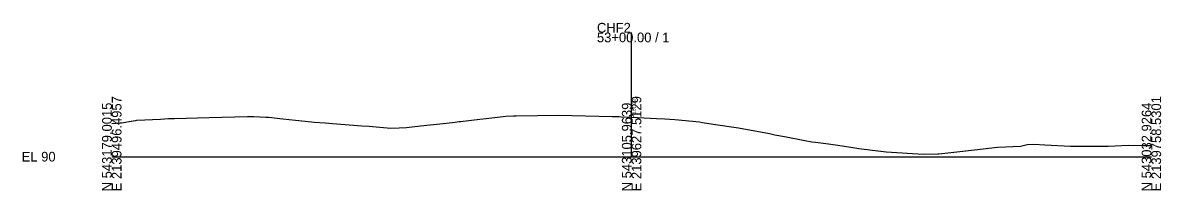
# Model space of a CAD drawing. Extents: x -12831 to 2303, y -10 to 39065.
# Drawn here: x 1974.3 to 2302.8, y 5990.3 to 6038.7 of the extents above; entities that cross this region are included whole.
import ezdxf

# ---------------------------------------------------------------- set-up
doc = ezdxf.new("R2010")
doc.units = 0
for name, color, linetype in [('RD_GPK_XS_Cell', 7, 'Continuous'), ('RD_XS_ExGround', 7, 'Continuous'), ('RD_XS_TX_Elev_EX', 7, 'Continuous')]:
    doc.layers.add(name, color=color, linetype=linetype)

msp = doc.modelspace()

# ---------------------------------------------------------------- linework, layer by layer
at = {"layer": 'RD_GPK_XS_Cell'}
for p, q in [((2150, 6000), (2150, 6035.84)), ((2000, 6000), (2150, 6000)), ((2150, 6000), (2300, 6000))]:
    msp.add_line(p, q, dxfattribs=at)
at = {"layer": 'RD_XS_ExGround'}
for p, q in [((2000, 6009.59), (2002.46, 6009.77)), ((2002.46, 6009.77), (2002.82, 6009.8)), ((2002.82, 6009.8), (2006.19, 6010.36)), ((2006.19, 6010.36), (2006.94, 6010.48)), ((2006.94, 6010.48), (2007.27, 6010.53)), ((2007.27, 6010.53), (2014.05, 6010.86)), ((2014.05, 6010.86), (2016.35, 6011)), ((2016.35, 6011), (2018.12, 6011.04)), ((2018.12, 6011.04), (2028.06, 6011.29)), ((2028.06, 6011.29), (2039.16, 6011.58)), ((2039.16, 6011.58), (2041, 6011.62)), ((2041, 6011.62), (2044.47, 6011.46)), ((2044.47, 6011.46), (2045.22, 6011.4)), ((2045.22, 6011.4), (2049.39, 6010.95)), ((2049.39, 6010.95), (2053.04, 6010.56)), ((2053.04, 6010.56), (2057.66, 6010.02)), ((2057.66, 6010.02), (2058.41, 6009.95)), ((2058.41, 6009.95), (2061.61, 6009.73)), ((2061.61, 6009.73), (2063.69, 6009.59)), ((2063.69, 6009.59), (2072.15, 6008.94)), ((2072.15, 6008.94), (2074.25, 6008.78)), ((2085.05, 6008.44), (2089.12, 6008.89)), ((2089.12, 6008.89), (2095.62, 6009.6)), ((2095.62, 6009.6), (2099.1, 6010.01)), ((2099.1, 6010.01), (2100.21, 6010.13)), ((2100.21, 6010.13), (2100.61, 6010.18)), ((2100.61, 6010.18), (2106.23, 6010.82)), ((2106.23, 6010.82), (2108.05, 6011.03)), ((2108.05, 6011.03), (2113.67, 6011.7)), ((2113.67, 6011.7), (2115.88, 6011.76)), ((2115.88, 6011.76), (2116.66, 6011.78)), ((2116.66, 6011.78), (2128.97, 6011.95)), ((2128.97, 6011.95), (2144.38, 6011.63)), ((2144.38, 6011.63), (2146.42, 6011.58)), ((2146.42, 6011.58), (2146.96, 6011.55)), ((2146.96, 6011.55), (2150, 6011.38)), ((2150, 6011.38), (2153.51, 6011.18)), ((2153.51, 6011.18), (2157.17, 6011.05)), ((2157.17, 6011.05), (2159.59, 6010.95)), ((2159.59, 6010.95), (2162.48, 6010.71)), ((2162.48, 6010.71), (2169.64, 6010.03)), ((2169.64, 6010.03), (2170.46, 6009.89)), ((2170.46, 6009.89), (2173.56, 6009.39)), ((2173.56, 6009.39), (2180.87, 6008.32)), ((2074.25, 6008.78), (2075.23, 6008.69)), ((2075.23, 6008.69), (2080.5, 6008.19)), ((2080.5, 6008.19), (2082.93, 6008.29)), ((2082.93, 6008.29), (2085.05, 6008.44)), ((2180.87, 6008.32), (2189.77, 6006.65)), ((2189.77, 6006.65), (2191.38, 6006.33)), ((2191.38, 6006.33), (2194.16, 6005.79)), ((2194.16, 6005.79), (2199.97, 6004.63)), ((2199.97, 6004.63), (2202.06, 6004.3)), ((2202.06, 6004.3), (2203.03, 6004.16)), ((2203.03, 6004.16), (2206.85, 6003.69)), ((2206.85, 6003.69), (2208.83, 6003.46)), ((2208.83, 6003.46), (2212.72, 6002.86)), ((2212.72, 6002.86), (2215.58, 6002.41)), ((2215.58, 6002.41), (2223.46, 6001.42)), ((2244.71, 6001.45), (2252.28, 6002.39)), ((2252.28, 6002.39), (2254.77, 6002.67)), ((2254.77, 6002.67), (2255.67, 6002.78)), ((2255.67, 6002.78), (2262.2, 6003.07)), ((2262.2, 6003.07), (2264.16, 6003.54)), ((2264.16, 6003.54), (2266.08, 6003.57)), ((2266.08, 6003.57), (2269.21, 6003.47)), ((2269.21, 6003.47), (2276.64, 6003.03)), ((2276.64, 6003.03), (2285.83, 6003.01)), ((2285.83, 6003.01), (2287.52, 6003.06)), ((2287.52, 6003.06), (2293.47, 6003.29)), ((2293.47, 6003.29), (2297.77, 6003.25)), ((2297.77, 6003.25), (2300, 6003.26)), ((2223.46, 6001.42), (2234.15, 6000.74)), ((2234.15, 6000.74), (2238.37, 6000.86)), ((2238.37, 6000.86), (2238.69, 6000.86)), ((2238.69, 6000.86), (2244.71, 6001.45))]:
    msp.add_line(p, q, dxfattribs=at)

# ---------------------------------------------------------------- texts
at = {"layer": 'RD_GPK_XS_Cell'}
for s, p in [('CHF2', (2140, 6035.84)), ('53+00.00 / 1', (2140, 6033.04)), ('EL 90', (1974, 5998.6))]:
    msp.add_text(s, height=2.8, dxfattribs=at).set_placement(p)
for s, p in [('N 543179.0015', (2000, 5990)), ('E 2139496.4957', (2002.8, 5990)), ('E 2139627.5129', (2152.8, 5990)), ('N 543032.9264', (2300, 5990)), ('E 2139758.5301', (2302.8, 5990)), ('N 543105.9639', (2150, 5990))]:
    msp.add_text(s, height=2.8, rotation=90, dxfattribs=at).set_placement(p)
at = {"layer": 'RD_XS_TX_Elev_EX'}
msp.add_text('101.38', height=1, rotation=90, dxfattribs=at).set_placement((2151.25, 6012.38))

doc.saveas('drawing.dxf')
